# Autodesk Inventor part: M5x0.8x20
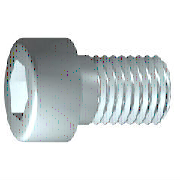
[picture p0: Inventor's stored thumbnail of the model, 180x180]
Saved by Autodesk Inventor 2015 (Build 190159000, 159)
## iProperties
IsCustomPart: 0
Created: 2015-11
Part Number: M5x0.8x20
Material: 스테인리스강
Description: 6각머리 태핑 나사
Document SubType Name: Modeling
Standard: KS B 1003
Designer: mdu
Standards Organization: KS
Language: ko-KR
Size Designation: M 5 x 20
Categories: <MemberInstance><Categories><Category DisplayName="조임쇠" InternalName="e4da775c-781d-43d5-af7c-5136215cf5a6" Mnemonic="FSTN"><Category DisplayName="볼트" InternalN
Density: 1 g/cm^3
Appearance: 반광택
Author: mdu
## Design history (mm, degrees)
sketch "스케치1"
  geometry: L1 (-1.167, 0)-(20, 0); L2 (20, 0)-(20, 2.5); L3 (20, 2.5)-(2, 2.5); L4 (2, 2.5)-(1.509, 2.5); L5 (1.509, 2.5)-(0, 2.5); L6 (0, 2.5)-(0, 4.25); L7 (0, 4.25)-(-5, 4.25); L8 (-5, 4.25)-(-5, 2.309); L9 (-5, 2.309)-(-2.5, 2.309); L10 (-2.5, 2.309)-(-1.167, 0); L11 (-10, 0)-(25, 0) reference; L12 (0, -0.85)-(0, 5.1) reference; L13 (2, 2.5)-(0, 2.5)
  constraints: 22 end point, 6 parallel, 2 collinear, 2 perpendicular, 1 horizontal, 1 point on line
  dimensions: "d1" = 18 distance from line of L3.end L2 (= GEL); "d2" = 0.49086 distance of L4.end L3.end (computed from GAL); "d3" = 5 distance between parallel lines of L8 L6 (= KOH); "d4" = 2.5 distance of L8.end L9.end (= INTI); "d5" = 60 deg angle of L10 L1; "d6" = 5 diameter of L3 L1 (= GD); "d7" = 5 diameter of L5 L1 (= BDM); "d8" = 4.6188 diameter of L9 L1 (= 1.1547 x SW); "d9" = 8.5 diameter of L7 L1 (= KOD); "d26" = 20 distance between parallel lines of L12 L2 (= NLG)
revolve "본체" sketch "스케치1" stored, may be unused: angle "d10" = 90 deg
sketch "스케치2"
  geometry: L1 (0, -5.95)-(0, 5.95) reference; L2 (-5.95, 0)-(5.95, 0) reference; L3 (2.309, 0)-(1.155, -2); L4 (1.155, -2)-(-1.155, -2); L5 (-1.155, -2)-(-2.309, 0); L6 (-2.309, 0)-(-1.155, 2); L7 (-1.155, 2)-(1.155, 2); L8 (1.155, 2)-(2.309, 0); 2 further points
  constraints: 12 end point, 1 coincident, 1 horizontal alignment, 1 point on line, 12 other
extrude "슬롯" join sketch "스케치2" stored distance "d11" = 10; taper "d12" = 0 deg
workplane "Work Plane1"
fillet "Fillet2" dims "d30" = 0.1 (= R)
body "Solid1"
fillet "모깎기1" dims "d17" = 0.5 (= RR)
feature "스레드" dims "d13" = 18 (= GEL), "d14" = 0
chamfer "모따기1" distance "d15" = 0.49076 (= -0.5 x SPD + 0.5 x GD); stored, may be unused: second distance "d16" = 0.49076 (= GUL), angle "d27" = 45 deg
other parameters: "GD" = 5 (= NND) [user parameter; used in 2 equation terms], "NLG" = 20 [user parameter; used in 1 equation term], "GEL" = 18 [user parameter; used in 2 equation terms], "KOD" = 8.5 [user parameter; used in 1 equation term], "KOH" = 5 [user parameter; used in 1 equation term], "INTI" = 2.5 [user parameter; used in 1 equation term], "GAL" = 0.49076 (= 0.61345 x PTC) [user parameter; used in 1 equation term], "GUL" = 0.49076 (= 0.61345 x PTC) [user parameter; used in 1 equation term], "BDM" = 5 (= NND) [user parameter; used in 1 equation term], "SW" = 4 [user parameter; used in 2 equation terms], "RR" = 0.5 [user parameter; used in 1 equation term], "SPD" = 4.01848 (= NND - 1.2269 x PTC) [user parameter; used in 1 equation term], "d19" = 0, "d28" = 0, "d29" = 0, "R" = 0.1 [user parameter; used in 1 equation term], "PHH" = 0.2 [user parameter], "GD1" = 4.01848 (= THREADDIA - 1.2269 x PTC) [user parameter], "THREADDIA" = 5 [user parameter; used in 1 equation term], "FAWI" = 45 deg [user parameter], "TPU" = 12.5 (computed from PTC) [user parameter], "PTC" = 0.8 [user parameter; used in 5 equation terms], "NND" = 5 [user parameter; used in 3 equation terms], "TOA" = 30 deg [user parameter], "E0" = 4.62 (= 1.155 x SW) [user parameter]
